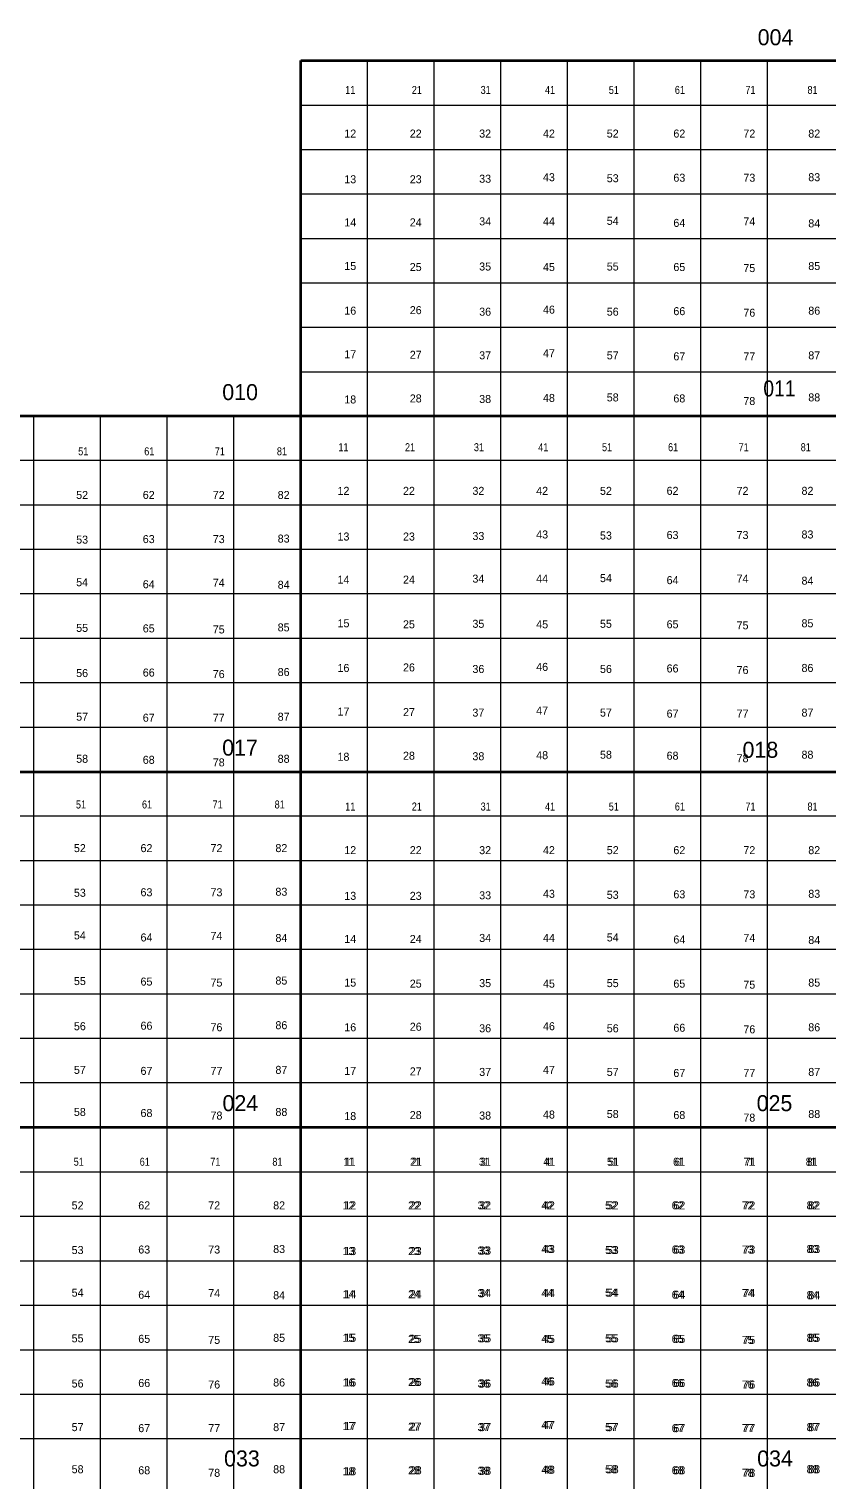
# Model space of a CAD drawing. Extents: x 639000 to 672000, y 222000 to 252000.
# Drawn here: x 643472 to 647960, y 242017 to 250177 of the extents above; entities that cross this region are included whole.
import ezdxf
from ezdxf.enums import TextEntityAlignment as Align

# ---------------------------------------------------------------- set-up
doc = ezdxf.new("R2010")
doc.units = 0
doc.header["$LTSCALE"] = 18
doc.layers.add('1', color=7, linetype='Continuous', lineweight=13)
doc.layers.add('2', color=7, linetype='Continuous')
doc.layers.add('29', color=7, linetype='Continuous')

msp = doc.modelspace()

# ---------------------------------------------------------------- linework, layer by layer
at = {"layer": '1', "lineweight": 35}
for p, q in [((645000, 250000), (657000, 250000)), ((645000, 224000), (645000, 250000)), ((660000, 248000), (639000, 248000)), ((639000, 246000), (663000, 246000)), ((666000, 244000), (639000, 244000))]:
    msp.add_line(p, q, dxfattribs=at)
at = {"layer": '1'}
for p, q in [((645375, 224000), (645375, 250000)), ((645750, 224000), (645750, 250000)), ((646125, 224000), (646125, 250000)), ((646500, 224000), (646500, 250000)), ((646875, 224000), (646875, 250000)), ((647250, 224000), (647250, 250000)), ((647625, 224000), (647625, 250000)), ((645000, 249750), (657000, 249750)), ((645000, 249500), (657000, 249500)), ((645000, 249250), (657000, 249250)), ((645000, 249000), (657000, 249000)), ((645000, 248750), (657000, 248750)), ((645000, 248500), (657000, 248500)), ((645000, 248250), (657000, 248250)), ((643500, 224000), (643500, 248000)), ((643875, 224000), (643875, 248000)), ((644250, 224000), (644250, 248000)), ((644625, 224000), (644625, 248000)), ((660000, 247750), (639000, 247750)), ((660000, 247500), (639000, 247500)), ((660000, 247250), (639000, 247250)), ((660000, 247000), (639000, 247000)), ((660000, 246750), (639000, 246750)), ((660000, 246500), (639000, 246500)), ((660000, 246250), (639000, 246250)), ((663000, 245750), (639000, 245750)), ((663000, 245500), (639000, 245500)), ((663000, 245250), (639000, 245250)), ((663000, 245000), (639000, 245000)), ((663000, 244750), (639000, 244750)), ((663000, 244500), (639000, 244500)), ((663000, 244250), (639000, 244250)), ((639000, 243750), (666000, 243750)), ((639000, 243500), (666000, 243500)), ((639000, 243250), (666000, 243250)), ((639000, 243000), (666000, 243000)), ((639000, 242750), (666000, 242750)), ((639000, 242500), (666000, 242500)), ((639000, 242250), (666000, 242250))]:
    msp.add_line(p, q, dxfattribs=at)

# ---------------------------------------------------------------- texts
at = {"layer": '2'}
for s, p in [('004', (647670.6, 250086.05)), ('010', (644659.4, 248090.34)), ('017', (644658.98, 246090.88)), ('018', (647585.38, 246078.81)), ('024', (644660.69, 244091.41)), ('025', (647664.9, 244091.41)), ('033', (644669.58, 242093.32))]:
    msp.add_text(s, height=90, dxfattribs=at).set_placement(p, align=Align.CENTER)
at = {"layer": '2', "width": 0.9}
msp.add_text('011', height=90, dxfattribs=at).set_placement((647692.42, 248111.06), align=Align.CENTER)
at = {"layer": '2'}
msp.add_text('034', height=90, rotation=0.36, dxfattribs=at).set_placement((647667.97, 242093.26), align=Align.CENTER)
at = {"layer": '29', "width": 0.85}
for s, p in [('11', (645278.78, 249812.3)), ('21', (645653.39, 249812.3)), ('31', (646040.69, 249812.3)), ('41', (646402.59, 249812.3)), ('51', (646761.33, 249812.3)), ('61', (647132.75, 249812.3)), ('71', (647529.58, 249812.3)), ('81', (647878.79, 249812.3)), ('11', (645240.69, 247802.98)), ('21', (645615.29, 247802.98)), ('31', (646002.59, 247802.98)), ('41', (646364.5, 247802.98)), ('51', (646723.23, 247802.98)), ('61', (647094.66, 247802.98)), ('71', (647491.49, 247802.98)), ('81', (647840.69, 247802.98)), ('51', (643777.19, 247779.89)), ('61', (644148.62, 247779.89)), ('71', (644545.45, 247779.89)), ('81', (644894.66, 247779.89)), ('51', (643764.5, 245793.67)), ('61', (644135.93, 245793.67)), ('71', (644532.75, 245793.67)), ('81', (644881.96, 245793.67)), ('11', (645278.78, 245782.12)), ('21', (645653.39, 245782.12)), ('31', (646040.69, 245782.12)), ('41', (646402.59, 245782.12)), ('51', (646761.33, 245782.12)), ('61', (647132.75, 245782.12)), ('71', (647529.58, 245782.12)), ('81', (647878.79, 245782.12)), ('51', (643751.8, 243784.35)), ('61', (644123.23, 243784.35)), ('71', (644520.05, 243784.35)), ('81', (644869.26, 243784.35)), ('11', (645269.26, 243784.35)), ('11', (645278.78, 243784.35)), ('21', (645643.86, 243784.35)), ('21', (645653.39, 243784.35)), ('31', (646031.16, 243784.35)), ('31', (646040.69, 243784.35)), ('41', (646393.07, 243784.35)), ('41', (646402.59, 243784.35)), ('51', (646751.8, 243784.35)), ('51', (646761.33, 243784.35)), ('61', (647123.23, 243784.35)), ('61', (647132.75, 243784.35)), ('71', (647520.05, 243784.35)), ('71', (647529.58, 243784.35)), ('81', (647869.26, 243784.35)), ('81', (647878.79, 243784.35))]:
    msp.add_text(s, height=45, dxfattribs=at).set_placement(p, align=Align.CENTER)
at = {"layer": '29'}
for s, p in [('12', (645278.78, 249566.91)), ('22', (645647.04, 249566.91)), ('32', (646037.51, 249566.91)), ('42', (646396.24, 249566.91)), ('52', (646754.97, 249566.91)), ('62', (647129.58, 249566.91)), ('72', (647523.23, 249566.91)), ('82', (647888.31, 249566.91)), ('13', (645278.78, 249309.97)), ('23', (645647.04, 249309.97)), ('33', (646037.51, 249312.85)), ('43', (646396.24, 249321.52)), ('53', (646754.97, 249315.74)), ('63', (647129.58, 249318.63)), ('73', (647523.23, 249318.63)), ('83', (647888.31, 249321.52)), ('14', (645278.78, 249067.46)), ('24', (645647.04, 249067.46)), ('34', (646037.51, 249073.24)), ('44', (646396.24, 249073.24)), ('54', (646754.97, 249076.12)), ('64', (647129.58, 249064.58)), ('74', (647523.23, 249073.24)), ('84', (647888.31, 249061.69)), ('15', (645278.78, 248822.07)), ('25', (645647.04, 248816.3)), ('35', (646037.51, 248819.19)), ('45', (646396.24, 248816.3)), ('55', (646754.97, 248819.19)), ('65', (647129.58, 248816.3)), ('75', (647523.23, 248810.52)), ('85', (647888.31, 248822.07)), ('16', (645278.78, 248570.91)), ('26', (645647.04, 248573.8)), ('36', (646037.51, 248565.14)), ('46', (646396.24, 248576.68)), ('56', (646754.97, 248565.14)), ('66', (647129.58, 248568.02)), ('76', (647523.23, 248559.36)), ('86', (647888.31, 248570.91)), ('17', (645278.78, 248325.52)), ('27', (645647.04, 248322.63)), ('37', (646037.51, 248319.74)), ('47', (646396.25, 248331.29)), ('57', (646754.98, 248319.74)), ('67', (647129.58, 248313.97)), ('77', (647523.23, 248313.97)), ('87', (647888.31, 248319.74)), ('18', (645278.78, 248071.47)), ('28', (645647.04, 248077.24)), ('38', (646037.51, 248074.35)), ('48', (646396.24, 248080.13)), ('58', (646754.97, 248083.02)), ('68', (647129.58, 248077.24)), ('78', (647523.23, 248062.81)), ('88', (647888.31, 248083.02)), ('12', (645240.69, 247557.59)), ('22', (645608.94, 247557.59)), ('32', (645999.42, 247557.59)), ('42', (646358.15, 247557.59)), ('52', (646716.88, 247557.59)), ('62', (647091.48, 247557.59)), ('72', (647485.13, 247557.59)), ('82', (647850.21, 247557.59)), ('52', (643770.84, 247534.5)), ('62', (644145.45, 247534.5)), ('72', (644539.1, 247534.5)), ('82', (644904.18, 247534.5)), ('13', (645240.69, 247300.65)), ('23', (645608.94, 247300.65)), ('33', (645999.42, 247303.54)), ('43', (646358.15, 247312.2)), ('53', (646716.88, 247306.43)), ('63', (647091.48, 247309.31)), ('73', (647485.14, 247309.31)), ('83', (647850.21, 247312.2)), ('53', (643770.84, 247283.33)), ('63', (644145.45, 247286.22)), ('73', (644539.1, 247286.22)), ('83', (644904.18, 247289.11)), ('14', (645240.69, 247058.15)), ('24', (645608.94, 247058.15)), ('34', (645999.42, 247063.92)), ('44', (646358.15, 247063.92)), ('54', (646716.88, 247066.81)), ('64', (647091.48, 247055.26)), ('74', (647485.14, 247063.92)), ('84', (647850.21, 247052.38)), ('54', (643770.84, 247043.71)), ('64', (644145.45, 247032.17)), ('74', (644539.1, 247040.83)), ('84', (644904.18, 247029.28)), ('15', (645240.69, 246812.76)), ('25', (645608.94, 246806.98)), ('35', (645999.42, 246809.87)), ('45', (646358.15, 246806.98)), ('55', (646716.88, 246809.87)), ('65', (647091.48, 246806.99)), ('85', (647850.21, 246812.76)), ('55', (643770.84, 246786.78)), ('65', (644145.45, 246783.89)), ('75', (644539.1, 246778.11)), ('85', (644904.18, 246789.66)), ('75', (647485.14, 246801.21)), ('16', (645240.69, 246561.59)), ('26', (645608.94, 246564.48)), ('46', (646358.15, 246567.37)), ('66', (647091.48, 246558.71)), ('86', (647850.21, 246561.59)), ('56', (643770.84, 246532.73)), ('66', (644145.45, 246535.61)), ('76', (644539.1, 246526.95)), ('86', (644904.18, 246538.5)), ('36', (645999.42, 246555.82)), ('56', (646716.88, 246555.82)), ('76', (647485.14, 246550.05)), ('17', (645240.69, 246316.2)), ('27', (645608.94, 246313.32)), ('47', (646358.15, 246321.98)), ('57', (643770.84, 246287.33)), ('67', (644145.45, 246281.56)), ('77', (644539.1, 246281.56)), ('87', (644904.18, 246287.33)), ('37', (645999.42, 246310.43)), ('57', (646716.88, 246310.43)), ('67', (647091.48, 246304.66)), ('77', (647485.14, 246304.66)), ('87', (647850.22, 246310.43)), ('48', (646358.15, 246070.81)), ('58', (646716.88, 246073.7)), ('88', (647850.21, 246073.7)), ('58', (643770.84, 246050.61)), ('68', (644145.45, 246044.83)), ('78', (644539.1, 246030.4)), ('88', (644904.18, 246050.61)), ('18', (645240.69, 246062.15)), ('28', (645608.94, 246067.93)), ('38', (645999.42, 246065.04)), ('68', (647091.48, 246067.93)), ('78', (647485.13, 246053.49)), ('52', (643758.15, 245548.28)), ('62', (644132.75, 245548.28)), ('72', (644526.4, 245548.28)), ('82', (644891.48, 245548.28)), ('12', (645278.78, 245536.73)), ('22', (645647.04, 245536.73)), ('32', (646037.51, 245536.73)), ('42', (646396.24, 245536.73)), ('52', (646754.97, 245536.73)), ('62', (647129.58, 245536.73)), ('72', (647523.23, 245536.73)), ('82', (647888.31, 245536.73)), ('53', (643758.15, 245297.11)), ('63', (644132.75, 245300)), ('73', (644526.4, 245300)), ('83', (644891.48, 245302.89)), ('13', (645278.78, 245279.79)), ('23', (645647.04, 245279.79)), ('33', (646037.51, 245282.68)), ('43', (646396.24, 245291.34)), ('53', (646754.97, 245285.56)), ('63', (647129.58, 245288.45)), ('73', (647523.23, 245288.45)), ('83', (647888.31, 245291.34)), ('54', (643758.15, 245057.49)), ('64', (644132.75, 245045.95)), ('74', (644526.4, 245054.61)), ('84', (644891.48, 245043.06)), ('14', (645278.78, 245037.29)), ('24', (645647.04, 245037.29)), ('34', (646037.51, 245043.06)), ('44', (646396.24, 245043.06)), ('54', (646754.97, 245045.95)), ('64', (647129.58, 245034.4)), ('74', (647523.23, 245043.06)), ('84', (647888.31, 245031.51)), ('55', (643758.15, 244800.56)), ('65', (644132.75, 244797.67)), ('75', (644526.4, 244791.9)), ('85', (644891.48, 244803.44)), ('15', (645278.78, 244791.9)), ('25', (645647.04, 244786.12)), ('35', (646037.51, 244789.01)), ('45', (646396.24, 244786.12)), ('55', (646754.97, 244789.01)), ('65', (647129.58, 244786.12)), ('75', (647523.23, 244780.35)), ('85', (647888.31, 244791.9)), ('56', (643758.15, 244546.51)), ('66', (644132.75, 244549.39)), ('76', (644526.4, 244540.73)), ('86', (644891.48, 244552.28)), ('16', (645278.78, 244540.73)), ('26', (645647.04, 244543.62)), ('36', (646037.51, 244534.96)), ('46', (646396.24, 244546.51)), ('56', (646754.97, 244534.96)), ('66', (647129.58, 244537.84)), ('76', (647523.23, 244529.18)), ('86', (647888.31, 244540.73)), ('57', (643758.15, 244301.11)), ('67', (644132.75, 244295.34)), ('77', (644526.4, 244295.34)), ('87', (644891.48, 244301.11)), ('17', (645278.78, 244295.34)), ('27', (645647.04, 244292.45)), ('37', (646037.51, 244289.57)), ('47', (646396.25, 244301.11)), ('57', (646754.98, 244289.57)), ('67', (647129.58, 244283.79)), ('77', (647523.23, 244283.79)), ('87', (647888.31, 244289.57)), ('58', (643758.15, 244064.39)), ('68', (644132.75, 244058.61)), ('78', (644526.4, 244044.18)), ('88', (644891.48, 244064.39)), ('18', (645278.78, 244041.29)), ('28', (645647.04, 244047.06)), ('38', (646037.51, 244044.18)), ('48', (646396.24, 244049.95)), ('58', (646754.97, 244052.84)), ('68', (647129.58, 244047.06)), ('78', (647523.23, 244032.63)), ('88', (647888.31, 244052.84)), ('52', (643745.45, 243538.96)), ('62', (644120.05, 243538.96)), ('72', (644513.7, 243538.96)), ('82', (644878.78, 243538.96)), ('12', (645269.25, 243538.96)), ('12', (645278.78, 243538.96)), ('22', (645637.51, 243538.96)), ('22', (645647.04, 243538.96)), ('32', (646027.99, 243538.96)), ('32', (646037.51, 243538.96)), ('42', (646386.72, 243538.96)), ('42', (646396.24, 243538.96)), ('52', (646745.45, 243538.96)), ('52', (646754.97, 243538.96)), ('62', (647120.05, 243538.96)), ('62', (647129.58, 243538.96)), ('72', (647513.7, 243538.96)), ('72', (647523.23, 243538.96)), ('82', (647878.78, 243538.96)), ('82', (647888.31, 243538.96)), ('53', (643745.45, 243287.8)), ('63', (644120.05, 243290.68)), ('73', (644513.7, 243290.68)), ('83', (644878.78, 243293.57)), ('13', (645269.26, 243282.02)), ('13', (645278.78, 243282.02)), ('23', (645637.51, 243282.02)), ('23', (645647.04, 243282.02)), ('33', (646027.99, 243284.91)), ('33', (646037.51, 243284.91)), ('43', (646386.72, 243293.57)), ('43', (646396.24, 243293.57)), ('53', (646745.45, 243287.8)), ('53', (646754.97, 243287.8)), ('63', (647120.05, 243290.68)), ('63', (647129.58, 243290.68)), ('73', (647513.7, 243290.68)), ('73', (647523.23, 243290.68)), ('83', (647878.78, 243293.57)), ('83', (647888.31, 243293.57)), ('54', (643745.45, 243048.18)), ('64', (644120.05, 243036.63)), ('74', (644513.7, 243045.29)), ('84', (644878.78, 243033.74)), ('14', (645269.26, 243039.52)), ('14', (645278.78, 243039.52)), ('24', (645637.51, 243039.52)), ('24', (645647.04, 243039.52)), ('34', (646027.99, 243045.29)), ('34', (646037.51, 243045.29)), ('44', (646386.72, 243045.29)), ('44', (646396.24, 243045.29)), ('54', (646745.45, 243048.18)), ('54', (646754.97, 243048.18)), ('64', (647120.05, 243036.63)), ('64', (647129.58, 243036.63)), ('74', (647513.7, 243045.29)), ('74', (647523.23, 243045.29)), ('84', (647878.78, 243033.74)), ('84', (647888.31, 243033.74)), ('55', (643745.45, 242791.24)), ('65', (644120.05, 242788.36)), ('75', (644513.7, 242782.58)), ('85', (644878.78, 242794.13)), ('15', (645269.26, 242794.13)), ('15', (645278.78, 242794.13)), ('25', (645637.51, 242788.35)), ('25', (645647.04, 242788.35)), ('35', (646027.99, 242791.24)), ('35', (646037.51, 242791.24)), ('45', (646386.72, 242788.35)), ('45', (646396.24, 242788.35)), ('55', (646745.45, 242791.24)), ('55', (646754.97, 242791.24)), ('65', (647120.05, 242788.36)), ('65', (647129.58, 242788.36)), ('75', (647513.7, 242782.58)), ('75', (647523.23, 242782.58)), ('85', (647878.78, 242794.13)), ('85', (647888.31, 242794.13)), ('56', (643745.45, 242537.19)), ('66', (644120.05, 242540.08)), ('76', (644513.7, 242531.42)), ('86', (644878.78, 242542.96)), ('16', (645269.26, 242542.96)), ('16', (645278.78, 242542.96)), ('26', (645637.51, 242545.85)), ('26', (645647.04, 242545.85)), ('36', (646027.99, 242537.19)), ('36', (646037.51, 242537.19)), ('46', (646386.72, 242548.74)), ('46', (646396.24, 242548.74)), ('56', (646745.45, 242537.19)), ('56', (646754.97, 242537.19)), ('66', (647120.05, 242540.08)), ('66', (647129.58, 242540.08)), ('76', (647513.7, 242531.42)), ('76', (647523.23, 242531.42)), ('86', (647878.78, 242542.96)), ('86', (647888.31, 242542.96)), ('57', (643745.45, 242291.8)), ('67', (644120.05, 242286.03)), ('77', (644513.7, 242286.03)), ('87', (644878.78, 242291.8)), ('17', (645269.26, 242297.57)), ('17', (645278.78, 242297.57)), ('27', (645637.51, 242294.69)), ('27', (645647.04, 242294.69)), ('37', (646027.99, 242291.8)), ('37', (646037.51, 242291.8)), ('47', (646386.72, 242303.35)), ('47', (646396.25, 242303.35)), ('57', (646745.45, 242291.8)), ('57', (646754.98, 242291.8)), ('67', (647120.05, 242286.03)), ('67', (647129.58, 242286.03)), ('77', (647513.7, 242286.03)), ('77', (647523.23, 242286.03)), ('87', (647878.78, 242291.8)), ('87', (647888.31, 242291.8)), ('58', (643745.45, 242055.07)), ('68', (644120.05, 242049.3)), ('78', (644513.7, 242034.86)), ('88', (644878.78, 242055.07)), ('18', (645269.25, 242043.52)), ('18', (645278.78, 242043.52)), ('28', (645637.51, 242049.3)), ('28', (645647.04, 242049.3)), ('38', (646027.99, 242046.41)), ('38', (646037.51, 242046.41)), ('48', (646386.72, 242052.18)), ('48', (646396.24, 242052.18)), ('58', (646745.45, 242055.07)), ('58', (646754.97, 242055.07)), ('68', (647120.05, 242049.3)), ('68', (647129.58, 242049.3)), ('78', (647513.7, 242034.86)), ('78', (647523.23, 242034.86)), ('88', (647878.78, 242055.07)), ('88', (647888.31, 242055.07))]:
    msp.add_text(s, height=45, dxfattribs=at).set_placement(p, align=Align.CENTER)

doc.saveas('drawing.dxf')
